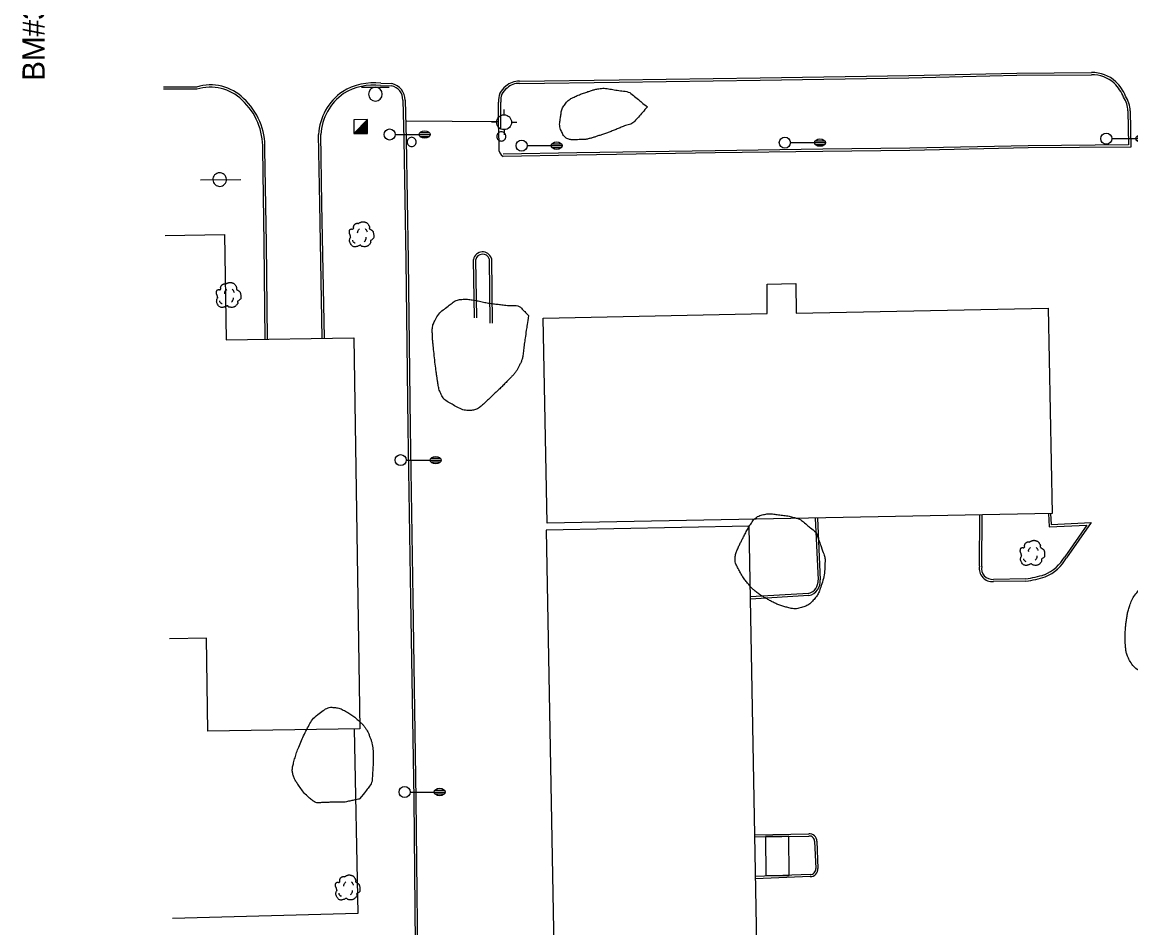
# Model space of a CAD drawing. Extents: x 2145380 to 2156929, y 139568 to 149130.
# Drawn here: x 2150211 to 2150511, y 140080.8 to 140325.9 of the extents above; entities that cross this region are included whole.
import ezdxf

# ---------------------------------------------------------------- set-up
doc = ezdxf.new("R2010")
doc.units = 0
for name, color, linetype in [('SURV_Text', 7, 'Continuous'), ('TOPO_Asphalt', 7, 'Continuous'), ('TOPO_Building', 7, 'Continuous'), ('TOPO_Curb Back', 7, 'Continuous'), ('TOPO_Fence', 7, 'Continuous'), ('TOPO_Light Pole', 7, 'Continuous'), ('TOPO_Misc', 7, 'Continuous'), ('TOPO_Sign', 7, 'Continuous'), ('TOPO_Tree', 7, 'Continuous'), ('TOPO_Tree Line', 7, 'Continuous'), ('TOPO_Water Fire Hydrant', 7, 'Continuous')]:
    doc.layers.add(name, color=color, linetype=linetype)

# ---------------------------------------------------------------- blocks, each defined once
blk = doc.blocks.new('LP')
at = {"layer": 'TOPO_Light Pole'}
blk.add_line((3.81, 0), (20.32, 0), dxfattribs=at)
for points in [[(20.32, 0), (27.94, 0)], [(20.32, 0), (23.5, 0)], [(20.83, 1.27), (27.43, 1.27)], [(20.83, 1.27), (23.5, 1.27)], [(23.71, 1.27), (27.43, 1.27)], [(23.71, 0), (27.94, 0)], [(20.83, -1.27), (27.43, -1.27)], [(20.83, -1.27), (23.5, -1.27)], [(23.71, -1.27), (27.43, -1.27)]]:
    blk.add_lwpolyline(points, dxfattribs=at)
blk.add_circle((0, 0), 3.81, dxfattribs=at)
blk.add_ellipse((24.13, 0), major_axis=(3.81, 0), ratio=0.666667, dxfattribs=at)
blk = doc.blocks.new('FIRHYD')
at = {"layer": 'TOPO_Water Fire Hydrant'}
for p, q in [((0, 10.2), (0, 17.3)), ((10.2, 0), (17.3, 0)), ((-10.2, 0), (-17.3, 0)), ((0, -10.2), (0, -17.3))]:
    blk.add_line(p, q, dxfattribs=at)
blk.add_circle((0, 0), 10.2, dxfattribs=at)
blk = doc.blocks.new('POST')
at = {"layer": 'TOPO_Misc'}
for start, end in [(89.99996, 180.00004), (179.99996, 270.00004), (359.99996, 90.00004), (269.99996, 0.00004)]:
    blk.add_arc((-0.01, 0.03), 3.16, start, end, dxfattribs=at)
blk = doc.blocks.new('TREE')
at = {"layer": 'TOPO_Tree'}
for points in [[(-14.1, -0.4), (-14.2, 0.5), (-14.4, 1.4), (-14.6, 2.3), (-14.8, 3.2), (-15.5, 4), (-15.7, 4.9), (-15.8, 5.6), (-15.7, 6.3), (-15.7, 7), (-15.6, 7.9), (-15.7, 8.8), (-15.1, 9.7), (-14.6, 10.4), (-13.8, 10.5), (-13, 10.7), (-12.2, 11), (-11.1, 10), (-10.4, 10.7), (-9.4, 11.7), (-10.3, 13.3), (-9.8, 14.4), (-9.6, 15.1), (-9.3, 15.9), (-8.8, 16.5), (-8.2, 17.3), (-7.5, 17.7), (-6.7, 18.1), (-6.1, 18.4), (-5.6, 18.6), (-5.1, 18.7), (-4.5, 18.7), (-4, 18.5), (-3.5, 18.1)], [(-3.5, 17.6), (-3.1, 18.3), (-2.6, 18.8), (-1.9, 19.2), (-1, 19.7), (-0.2, 20), (0.7, 20.2), (1.6, 20.5), (2.5, 20.8), (3.4, 20.8), (4.1, 20.7), (4.8, 20.5), (5.5, 20.2), (6.4, 19.9), (7.3, 19.7), (8.2, 19.2), (9.4, 18.4), (10, 17.2), (10.8, 16), (11.2, 15.3), (11.6, 14.6), (11.9, 13.9), (12.2, 13.1), (11.4, 12), (11.9, 11.2), (12, 11), (12.2, 10.9), (12.4, 10.7), (12.9, 10.4), (13.5, 10), (14, 9.7), (14.7, 9.2), (15.4, 8.7), (16.1, 8.1), (16.7, 7.5), (16.9, 6.7), (17.1, 6), (17.6, 4.4), (17.7, 2.8), (17.7, 1.2), (17.7, -0.2), (17.8, -2.2), (16.6, -3), (15.5, -3.8), (14.3, -4.6), (13.2, -5.3)], [(13.2, -5.3), (13.3, -5.8), (13.4, -6.3), (13.4, -6.7), (13.8, -8.5), (12.2, -10), (10.8, -11.5), (10, -12.3), (9.1, -12.8), (8.2, -13.1), (6, -13.8), (3.3, -13.6), (1.3, -13.1), (0.5, -12.9), (-0.1, -11.4), (-0.8, -11.5), (-2, -11.6), (-3.3, -12.8), (-4.5, -13.1), (-6.1, -13.5), (-7.8, -14), (-9.3, -13.6), (-11.4, -13.1), (-12.8, -11.4), (-14.1, -9.4), (-15.3, -7.3), (-15.6, -5.1), (-15.1, -3), (-14.9, -1.9), (-13.9, -0.8), (-13.5, 0.1)], [(-4.2, 5.1), (-4.5, 6.1), (-4.3, 7.2), (-3.8, 8.2), (-3.3, 9.3), (-2.7, 10.3), (-1.6, 11)], [(5.9, 11.2), (6.5, 10.7), (7, 10.2), (7.4, 9.5), (7.9, 8.6), (8.3, 7.6), (8.5, 6.6)], [(-11.4, -4.5), (-11.5, -5.4), (-11, -6.3), (-10.1, -7.2), (-9.3, -8), (-8.5, -8.3), (-7.7, -8.1)], [(4.8, -6.3), (5.7, -5.7), (6.3, -4.9), (6.8, -3.9), (7.4, -2.8), (7.6, -1.7), (7.5, -0.6)]]:
    blk.add_open_spline(points, degree=3, dxfattribs=at)

msp = doc.modelspace()

# ---------------------------------------------------------------- linework, layer by layer
at = {"layer": 'TOPO_Asphalt'}
msp.add_line((2150339.92, 140298.91), (2150314.77, 140299.09), dxfattribs=at)
msp.add_lwpolyline([(2150339.93, 140297.22), (2150339.98, 140291.88)], dxfattribs=at)
msp.add_arc((2150342.36, 140291.66), 2.39, 174.7377, 239.9631, dxfattribs=at)
at = {"layer": 'TOPO_Building'}
msp.add_lwpolyline([(2150249.66, 140268.17), (2150265.72, 140268.42), (2150266.15, 140239.97), (2150300.71, 140240.49), (2150302.32, 140134.63), (2150261.27, 140134.01), (2150260.89, 140159.19), (2150250.83, 140159.04)], dxfattribs=at)
for points in [[(2150420.46, 140247.17), (2150488.6, 140248.49), (2150489.68, 140192.93), (2150353.06, 140190.28), (2150351.99, 140245.84), (2150412.61, 140247.05), (2150412.6, 140255.05), (2150420.34, 140255.19)], [(2150352.76, 140188.44), (2150355.67, 140031.04), (2150410.6, 140032.05), (2150407.69, 140189.46)]]:
    msp.add_lwpolyline(points, close=True, dxfattribs=at)
at = {"layer": 'TOPO_Curb Back'}
for points in [[(2150345.57, 140309.36), (2150372.54, 140309.69), (2150410.72, 140310.27), (2150450.92, 140310.9), (2150480.16, 140311.55), (2150500.35, 140311.68)], [(2150345.58, 140309.96), (2150372.53, 140310.29), (2150410.71, 140310.87), (2150450.91, 140311.5), (2150480.15, 140312.15), (2150500.34, 140312.28)], [(2150307.97, 140308.82), (2150310.91, 140308.72)], [(2150308.02, 140309.42), (2150310.99, 140309.32)], [(2150258.19, 140308.37), (2150249.26, 140308.36)], [(2150258.28, 140307.77), (2150249.26, 140307.76)], [(2150314.01, 140304.81), (2150314.31, 140294.26), (2150314.84, 140261.44), (2150315.34, 140216.16), (2150316.1, 140169.9), (2150316.95, 140115.57), (2150317.56, 140056.63), (2150318.47, 140015.75), (2150318.91, 139970.85), (2150319.59, 139936.26), (2150345.99, 139936.73), (2150379.22, 139937.18), (2150415.3, 139937.61), (2150440.34, 139938.14), (2150484.48, 139938.5), (2150535.71, 139939.38)], [(2150314.61, 140304.82), (2150314.91, 140294.28), (2150315.44, 140261.45), (2150315.94, 140216.16), (2150316.7, 140169.91), (2150317.55, 140115.57), (2150318.16, 140056.64), (2150319.07, 140015.76), (2150319.51, 139970.86), (2150320.18, 139936.88), (2150345.98, 139937.33), (2150379.21, 139937.78), (2150415.29, 139938.21), (2150440.33, 139938.74), (2150484.47, 139939.1), (2150535.7, 139939.98)], [(2150339.93, 140297.22), (2150339.91, 140304.27)], [(2150340.53, 140297.22), (2150340.51, 140304.31)], [(2150510.2, 140301.9), (2150510.38, 140292.68), (2150483.18, 140292.47), (2150451.16, 140291.79), (2150427.66, 140291.56), (2150398.49, 140291.13), (2150361.08, 140290.56), (2150341.16, 140290.19)], [(2150510.8, 140301.91), (2150510.99, 140292.08), (2150483.19, 140291.87), (2150451.17, 140291.19), (2150427.66, 140290.96), (2150398.49, 140290.53), (2150361.09, 140289.96), (2150341.17, 140289.59)], [(2150292.18, 140240.36), (2150291.52, 140276.74), (2150291.19, 140295.54)], [(2150292.78, 140240.37), (2150292.12, 140276.75), (2150291.79, 140295.53)], [(2150276.78, 140240.13), (2150276.51, 140266), (2150276.08, 140291.58)], [(2150277.38, 140240.14), (2150277.11, 140266.01), (2150276.68, 140291.58)], [(2150333.43, 140245.9), (2150333.12, 140261.7)], [(2150334.03, 140245.91), (2150333.72, 140261.65)], [(2150337.35, 140261.88), (2150337.57, 140244.42)], [(2150337.95, 140261.98), (2150338.17, 140244.43)], [(2150425.61, 140191.68), (2150426.35, 140174.93)], [(2150426.21, 140191.7), (2150426.95, 140174.96)], [(2150470.04, 140178.67), (2150470.14, 140192.55)], [(2150470.64, 140178.61), (2150470.74, 140192.55)], [(2150488.7, 140192.9), (2150488.89, 140189.28), (2150499.06, 140189.79), (2150493.09, 140181.24)], [(2150489.3, 140192.92), (2150489.46, 140189.91), (2150500.26, 140190.45), (2150493.6, 140180.91)], [(2150482.57, 140175.22), (2150473.79, 140175.11)], [(2150482.62, 140174.62), (2150473.82, 140174.51)], [(2150423.8, 140171.31), (2150408.05, 140170.33)], [(2150423.89, 140170.72), (2150408.07, 140169.73)], [(2150409.24, 140105.98), (2150423.85, 140106.23)], [(2150409.25, 140105.38), (2150423.88, 140105.63)], [(2150425.42, 140104.21), (2150425.72, 140096.83)], [(2150426.02, 140104.21), (2150426.32, 140096.88)], [(2150424.22, 140095.24), (2150409.44, 140094.65)], [(2150424.22, 140094.64), (2150409.46, 140094.05)]]:
    msp.add_lwpolyline(points, dxfattribs=at)
for centre, radius, start, end in [((2150500.64, 140303.08), 9.2, 47.0489, 91.8924), ((2150500.64, 140303.08), 8.6, 47.0942, 91.945), ((2150261.96, 140296.12), 12.82, 45.6383, 107.1027), ((2150306.22, 140293.01), 16.51, 83.7465, 121.3206), ((2150306.22, 140293.01), 15.9, 83.6638, 121.2508), ((2150310, 140304.82), 4.01, 359.8783, 76.7774), ((2150310, 140304.82), 4.61, 359.9966, 77.5444), ((2150344.43, 140304.82), 4.55, 124.552, 186.9825), ((2150345.36, 140304.85), 5.11, 87.5076, 133.3508), ((2150345.36, 140304.85), 4.51, 87.3018, 133.9373), ((2150498.7, 140301.38), 11.17, 22.2118, 45.7247), ((2150498.7, 140301.38), 11.77, 22.498, 45.7583), ((2150261.96, 140296.12), 12.22, 45.6006, 107.5207), ((2150306.39, 140294.65), 15.23, 125.0921, 176.6305), ((2150306.39, 140294.65), 14.63, 125.1695, 176.5425), ((2150344.43, 140304.82), 3.95, 123.8831, 187.4881), ((2150503.2, 140301.74), 7, 1.252, 33.4792), ((2150503.2, 140301.74), 7.6, 1.2467, 33.0291), ((2150258.65, 140292.05), 17.44, 358.4469, 47.1664), ((2150258.65, 140292.05), 18.04, 358.4888, 47.1406), ((2150335.57, 140261.24), 2.49, 17.2622, 169.5159), ((2150335.57, 140261.24), 1.89, 19.7264, 167.7946), ((2150483.21, 140186.84), 11.36, 292.8542, 330.4208), ((2150483.21, 140186.84), 11.96, 292.7186, 330.2842), ((2150473.52, 140178.03), 3.54, 169.5913, 274.9213), ((2150473.52, 140178.03), 2.94, 168.6189, 275.3328), ((2150422.94, 140174.63), 3.43, 284.4972, 4.8902), ((2150422.94, 140174.63), 4.03, 283.6482, 4.7077), ((2150477.86, 140207.34), 32.46, 278.3368, 287.4939), ((2150477.86, 140207.33), 33.06, 278.267, 287.5426), ((2150424.02, 140104.24), 2, 359.209, 94.9419), ((2150424.02, 140104.24), 1.4, 358.5992, 95.7188), ((2150424.29, 140096.67), 2.04, 267.9427, 5.8091), ((2150424.29, 140096.67), 1.44, 267.1207, 6.474)]:
    msp.add_arc(centre, radius, start, end, dxfattribs=at)
at = {"layer": 'TOPO_Fence'}
msp.add_lwpolyline([(2150300.84, 140134.61), (2150301.79, 140084.62), (2150251.66, 140083.33)], dxfattribs=at)
at = {"layer": 'TOPO_Misc'}
for p, q in [((2150300.72, 140295.79), (2150304.45, 140299.54)), ((2150301.62, 140296.7), (2150304.46, 140296.7)), ((2150301.81, 140296.89), (2150304.46, 140296.89)), ((2150302, 140297.08), (2150304.46, 140297.08)), ((2150302.18, 140297.26), (2150304.45, 140297.26)), ((2150302.37, 140297.45), (2150304.45, 140297.45)), ((2150302.56, 140297.64), (2150304.45, 140297.64)), ((2150302.74, 140297.82), (2150304.45, 140297.82)), ((2150302.93, 140298.01), (2150304.45, 140298.01)), ((2150303.11, 140298.19), (2150304.45, 140298.19)), ((2150303.3, 140298.38), (2150304.45, 140298.38)), ((2150303.48, 140298.57), (2150304.45, 140298.57)), ((2150303.68, 140298.76), (2150304.45, 140298.76)), ((2150303.87, 140298.95), (2150304.45, 140298.95)), ((2150304.05, 140299.13), (2150304.45, 140299.13)), ((2150304.24, 140299.32), (2150304.45, 140299.32)), ((2150304.42, 140299.5), (2150304.45, 140299.5)), ((2150300.87, 140295.95), (2150304.46, 140295.95)), ((2150301.06, 140296.14), (2150304.46, 140296.14)), ((2150301.24, 140296.33), (2150304.46, 140296.33)), ((2150301.43, 140296.52), (2150304.46, 140296.52))]:
    msp.add_line(p, q, dxfattribs=at)
msp.add_lwpolyline([(2150304.46, 140295.8), (2150304.45, 140299.54), (2150300.71, 140299.53), (2150300.72, 140295.79), (2150304.46, 140295.8)], dxfattribs=at)
at = {"layer": 'TOPO_Sign'}
for points in [[(2150302.83, 140308.3), (2150310.32, 140308.31)], [(2150304.71, 140306.43), (2150304.71, 140306.43)], [(2150306.58, 140308.3), (2150306.58, 140308.3)], [(2150308.44, 140306.43), (2150308.44, 140306.43)], [(2150306.58, 140304.56), (2150306.58, 140304.56)], [(2150259.29, 140283.29), (2150270.17, 140283.35)]]:
    msp.add_lwpolyline(points, dxfattribs=at)
msp.add_lwpolyline([(2150418.55, 140094.98), (2150418.49, 140105.57), (2150412.14, 140105.54), (2150412.2, 140094.95)], close=True, dxfattribs=at)
for centre, radius, start, end in [((2150306.58, 140306.43), 1.87, 90, 180), ((2150306.58, 140306.43), 1.87, 180, 270), ((2150306.58, 140306.43), 1.87, 360, 90), ((2150306.58, 140306.43), 1.87, 270, 0), ((2150264.43, 140283.32), 1.84, 47.4196, 227.4196), ((2150264.43, 140283.32), 1.84, 227.4196, 47.4196)]:
    msp.add_arc(centre, radius, start, end, dxfattribs=at)
at = {"layer": 'TOPO_Tree Line'}
for points in [[(2150380.16, 140302.97), (2150378.9, 140304.01), (2150377.65, 140305.06), (2150376.39, 140306.11), (2150375.11, 140307.18), (2150373.26, 140307.27), (2150371.61, 140307.56), (2150370.06, 140307.83), (2150368.47, 140308.12), (2150366.94, 140307.88), (2150365.98, 140307.73), (2150365.05, 140307.44), (2150364.12, 140307.13), (2150362.92, 140306.73), (2150361.77, 140306.3), (2150360.62, 140305.77), (2150359.47, 140305.25), (2150358.5, 140304.59), (2150357.69, 140303.48), (2150356.98, 140302.49), (2150356.85, 140301.42), (2150356.69, 140300.35), (2150356.49, 140299.01), (2150356.35, 140297.58), (2150356.97, 140296.23), (2150357.42, 140295.27), (2150358.14, 140294.42), (2150359.13, 140294.2), (2150359.98, 140294.01), (2150360.84, 140294.06), (2150361.7, 140294.12), (2150362.59, 140294.19), (2150363.5, 140294.17), (2150364.38, 140294.39), (2150365.28, 140294.63), (2150366.14, 140294.9), (2150367.01, 140295.2), (2150368.05, 140295.54), (2150369.09, 140295.89), (2150370.12, 140296.27), (2150371.21, 140296.67), (2150372.27, 140297.14), (2150373.34, 140297.59), (2150374.58, 140298.1), (2150376.07, 140298.34), (2150376.95, 140299.34), (2150378.02, 140300.55), (2150379.09, 140301.76), (2150380.16, 140302.97), (2150380.16, 140302.97)], [(2150348.01, 140246.51), (2150347.48, 140247.06), (2150346.95, 140247.61), (2150346.42, 140248.16), (2150345.24, 140249.4), (2150343.13, 140249.13), (2150341.44, 140249.36), (2150340.14, 140249.54), (2150338.83, 140249.64), (2150337.55, 140249.84), (2150336.15, 140250.06), (2150334.77, 140250.41), (2150333.37, 140250.65), (2150332.16, 140250.87), (2150330.9, 140251.01), (2150329.68, 140250.86), (2150328.43, 140250.71), (2150327.38, 140249.91), (2150326.31, 140249.1), (2150324.86, 140248), (2150323.65, 140247), (2150322.79, 140245.37), (2150322.2, 140244.25), (2150321.94, 140243.12), (2150321.98, 140241.95), (2150322.01, 140240.81), (2150322.07, 140239.67), (2150322.19, 140238.54), (2150322.44, 140236.23), (2150322.69, 140233.92), (2150322.98, 140231.61), (2150323.09, 140230.66), (2150323.25, 140229.72), (2150323.39, 140228.77), (2150323.58, 140227.54), (2150323.82, 140226.34), (2150324.39, 140225.17), (2150325.04, 140223.81), (2150326.28, 140223.12), (2150327.64, 140222.32), (2150329.1, 140221.46), (2150330.59, 140220.8), (2150332.05, 140220.83), (2150333.1, 140220.85), (2150334.28, 140221.24), (2150335.17, 140221.99), (2150336.03, 140222.72), (2150336.75, 140223.44), (2150337.53, 140224.18), (2150338.28, 140224.88), (2150339.03, 140225.58), (2150339.77, 140226.29), (2150340.66, 140227.13), (2150341.52, 140228), (2150342.38, 140228.87), (2150343.05, 140229.54), (2150343.69, 140230.23), (2150344.3, 140230.95), (2150344.85, 140231.6), (2150345.25, 140232.34), (2150345.61, 140233.11), (2150345.98, 140233.92), (2150346.33, 140234.74), (2150346.46, 140235.62), (2150346.7, 140237.2), (2150346.85, 140238.78), (2150347.08, 140240.35), (2150347.39, 140242.4), (2150347.7, 140244.46), (2150348.01, 140246.51)], [(2150425.86, 140187.8), (2150424.58, 140188.85), (2150423.3, 140189.89), (2150422.02, 140190.94), (2150421.34, 140191.49), (2150420.44, 140191.7), (2150419.58, 140191.92), (2150418.15, 140192.29), (2150416.71, 140192.48), (2150415.26, 140192.66), (2150414.05, 140192.81), (2150412.8, 140192.89), (2150411.58, 140192.62), (2150410.27, 140192.33), (2150409.07, 140191.49), (2150408.32, 140190.36), (2150407.55, 140189.2), (2150406.93, 140188.03), (2150406.3, 140186.83), (2150405.84, 140185.94), (2150405.4, 140185.1), (2150404.97, 140184.17), (2150404.48, 140183.13), (2150404.04, 140182.07), (2150403.94, 140181.01), (2150403.82, 140179.82), (2150404.42, 140178.62), (2150405.06, 140177.43), (2150405.69, 140176.23), (2150406.33, 140175.27), (2150407.13, 140174.27), (2150407.75, 140173.48), (2150408.37, 140172.72), (2150409.14, 140172.08), (2150410.06, 140171.31), (2150411.04, 140170.68), (2150412.07, 140170.07), (2150413.02, 140169.51), (2150413.97, 140169.02), (2150414.97, 140168.54), (2150416, 140168.06), (2150417.07, 140167.75), (2150418.14, 140167.47), (2150419.43, 140167.13), (2150420.86, 140167.14), (2150422.17, 140167.56), (2150423.4, 140167.95), (2150424.4, 140168.66), (2150425.28, 140169.7), (2150426.13, 140170.71), (2150426.66, 140171.71), (2150427.05, 140172.9), (2150427.7, 140174.85), (2150428.12, 140176.81), (2150428.2, 140178.79), (2150428.24, 140179.79), (2150428.27, 140180.86), (2150427.94, 140181.81), (2150427.25, 140183.81), (2150426.56, 140185.81), (2150425.86, 140187.8)], [(2150529.79, 140180.19), (2150527.76, 140179.6), (2150525.73, 140179.02), (2150523.7, 140178.43), (2150522.69, 140178.13), (2150521.78, 140177.59), (2150520.83, 140177.12), (2150519.11, 140176.26), (2150517.45, 140175.34), (2150515.79, 140174.34), (2150514.9, 140173.81), (2150514.14, 140173.15), (2150513.41, 140172.38), (2150512.27, 140171.17), (2150511.39, 140169.84), (2150510.82, 140168.3), (2150510.39, 140167.18), (2150510.11, 140166.05), (2150509.92, 140164.88), (2150509.74, 140163.72), (2150509.6, 140162.57), (2150509.52, 140161.41), (2150509.41, 140159.81), (2150509.46, 140158.21), (2150509.58, 140156.61), (2150509.66, 140155.57), (2150509.93, 140154.59), (2150510.43, 140153.61), (2150511.22, 140152.06), (2150512.33, 140150.96), (2150513.79, 140149.98), (2150514.54, 140149.48), (2150515.29, 140149.09), (2150516.13, 140149.02), (2150517.62, 140148.9), (2150519.11, 140148.86), (2150520.6, 140148.88), (2150522.59, 140148.92), (2150524.59, 140148.83), (2150526.58, 140149.07), (2150527.52, 140149.19), (2150528.45, 140149.32), (2150529.39, 140149.46), (2150530.74, 140149.65), (2150532.09, 140149.84), (2150533.44, 140150.05), (2150534.6, 140150.23), (2150535.67, 140150.71), (2150536.76, 140151.17), (2150537.9, 140151.65), (2150538.95, 140152.23), (2150539.97, 140152.95), (2150541.39, 140153.94), (2150542.5, 140155.11), (2150543.54, 140156.54), (2150544.1, 140157.31), (2150544.49, 140158.11), (2150544.73, 140159.01), (2150545.13, 140160.45), (2150545.24, 140161.93), (2150545.14, 140163.37), (2150545.06, 140164.35), (2150544.96, 140165.36), (2150544.53, 140166.31), (2150544.12, 140167.21), (2150543.67, 140168.02), (2150543.2, 140168.86), (2150542.04, 140170.9), (2150540.86, 140172.9), (2150539.63, 140174.91), (2150539.03, 140175.9), (2150538.5, 140177.06), (2150537.44, 140177.6), (2150536.31, 140178.18), (2150535.13, 140178.49), (2150533.95, 140178.86), (2150532.56, 140179.31), (2150531.18, 140179.75), (2150529.79, 140180.19)], [(2150302.31, 140115.66), (2150303.13, 140116.72), (2150303.95, 140117.78), (2150304.78, 140118.84), (2150305.72, 140120.05), (2150305.73, 140121.79), (2150305.84, 140123.33), (2150305.94, 140124.69), (2150305.99, 140126.05), (2150305.97, 140127.42), (2150305.96, 140128.26), (2150305.92, 140129.1), (2150305.8, 140129.94), (2150305.67, 140130.8), (2150305.39, 140131.6), (2150305.09, 140132.42), (2150304.77, 140133.27), (2150304.42, 140134.08), (2150303.9, 140134.84), (2150303.41, 140135.57), (2150302.81, 140136.15), (2150302.16, 140136.74), (2150301.2, 140137.61), (2150300.29, 140138.32), (2150299.1, 140139.04), (2150297.89, 140139.77), (2150296.66, 140140.31), (2150295.44, 140140.43), (2150294.1, 140140.55), (2150292.76, 140139.88), (2150291.43, 140138.85), (2150289.73, 140137.51), (2150288.86, 140136.15), (2150288, 140134.49), (2150287.12, 140132.76), (2150286.35, 140131.05), (2150285.66, 140129.24), (2150285.13, 140127.87), (2150284.71, 140126.49), (2150284.36, 140125.08), (2150284.11, 140124.11), (2150284.05, 140123.03), (2150284.34, 140122.06), (2150284.62, 140121.11), (2150285.14, 140120.3), (2150285.72, 140119.47), (2150286.66, 140118.11), (2150287.53, 140116.94), (2150288.84, 140115.84), (2150289.62, 140115.18), (2150290.48, 140114.6), (2150291.44, 140114.64), (2150292.57, 140114.68), (2150293.7, 140114.73), (2150294.83, 140114.78), (2150296.25, 140114.85), (2150297.7, 140114.68), (2150299.09, 140114.97), (2150300.16, 140115.2), (2150301.23, 140115.43), (2150302.31, 140115.66), (2150302.31, 140115.66)]]:
    msp.add_open_spline(points, degree=3, dxfattribs=at)

# ---------------------------------------------------------------- block references
at = {"layer": 'TOPO_Light Pole', "xscale": 0.39370000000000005, "yscale": 0.3937000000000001}
for p in [(2150310.42, 140295.52), (2150346.13, 140292.5), (2150417.37, 140293.32), (2150504.34, 140294.41), (2150313.4, 140207.38), (2150314.47, 140117.54)]:
    msp.add_blockref('LP', p, dxfattribs=at)
at = {"layer": 'TOPO_Misc', "xscale": 0.39370000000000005, "yscale": 0.3937000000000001}
for p in [(2150316.4, 140293.5), (2150340.67, 140294.97)]:
    msp.add_blockref('POST', p, dxfattribs=at)
at = {"layer": 'TOPO_Tree', "xscale": 0.19685000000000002, "yscale": 0.19685000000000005}
for p in [(2150302.63, 140267.83), (2150266.66, 140251.41), (2150484.18, 140181.58), (2150298.9, 140091.02)]:
    msp.add_blockref('TREE', p, dxfattribs=at)
at = {"layer": 'TOPO_Water Fire Hydrant', "xscale": 0.19685000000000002, "yscale": 0.19685000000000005}
msp.add_blockref('FIRHYD', (2150341.41, 140298.84), dxfattribs=at)

# ---------------------------------------------------------------- texts
at = {"layer": 'SURV_Text'}
msp.add_text('BM#33', height=6, rotation=90, dxfattribs=at).set_placement((2150217.08, 140310.04))

doc.saveas('drawing.dxf')
